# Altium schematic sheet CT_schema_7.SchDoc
size 287 x 160 mm
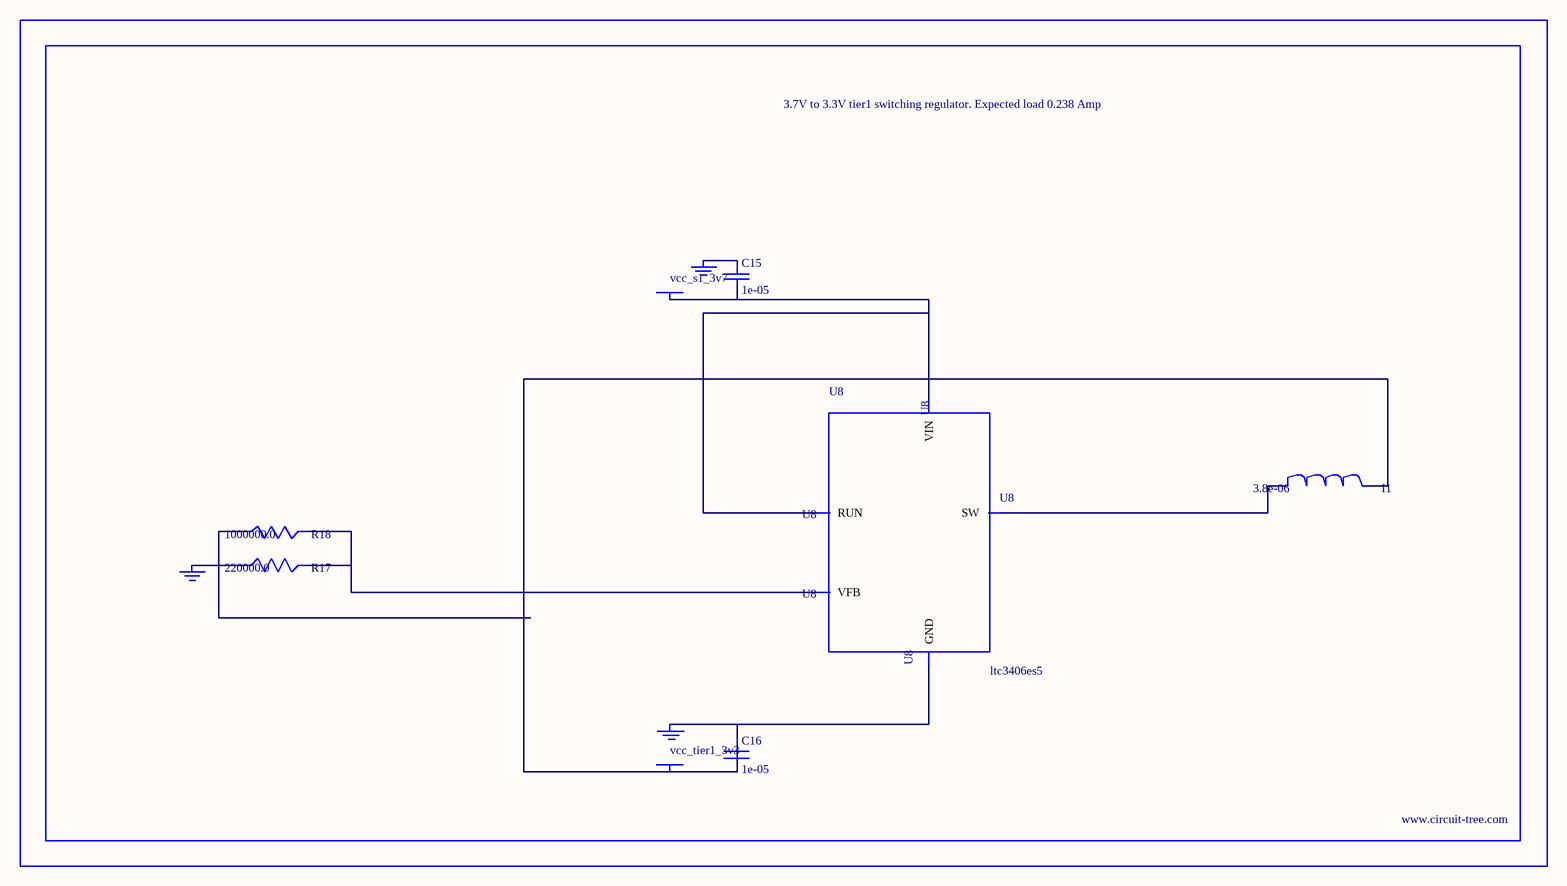
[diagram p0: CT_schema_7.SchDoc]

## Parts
BORDER6  (no value)
C15  1e-05  [C0805]
C16  1e-05  [C0805]
GND_INSTANCE_6_0  (no value)
GND_INSTANCE_6_1  (no value)
GND_INSTANCE_6_2  (no value)
I1  3.8e-06  [DR1040]
POWER_INSTANCE_6_0  vcc_tier1_3v3
POWER_INSTANCE_6_1  vcc_s1_3v7
R17  220000.0  [R0603]
R18  1000000.0  [R0603]
U8  ltc3406es5  [TSOT-23-5]

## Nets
NetC15_1: C15.1 GND_INSTANCE_6_1.0(GND)
NetC15_2: C15.2 POWER_INSTANCE_6_1.0(PWR) U8.1(RUN) U8.4(VIN)
NetC16_1: C16.1 GND_INSTANCE_6_0.0(GND) U8.2(GND)
NetC16_2: C16.2 I1.2 POWER_INSTANCE_6_0.0(PWR) R18.1
NetGND_INSTANCE_6_2_0: GND_INSTANCE_6_2.0(GND) R17.1
NetI1_1: I1.1 U8.3(SW)
NetR17_2: R17.2 R18.2 U8.5(VFB)

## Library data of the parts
BORDER6 = BORDER_PAGE6
C15 C16 = C0805C106K8RACTU
GND_INSTANCE_6_0-GND_INSTANCE_6_2 = GND
I1 = DR1040-3R8-R
POWER_INSTANCE_6_0 POWER_INSTANCE_6_1 = PWR
R17 = RC0603JR-07220KL
R18 = RC0603JR-071ML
